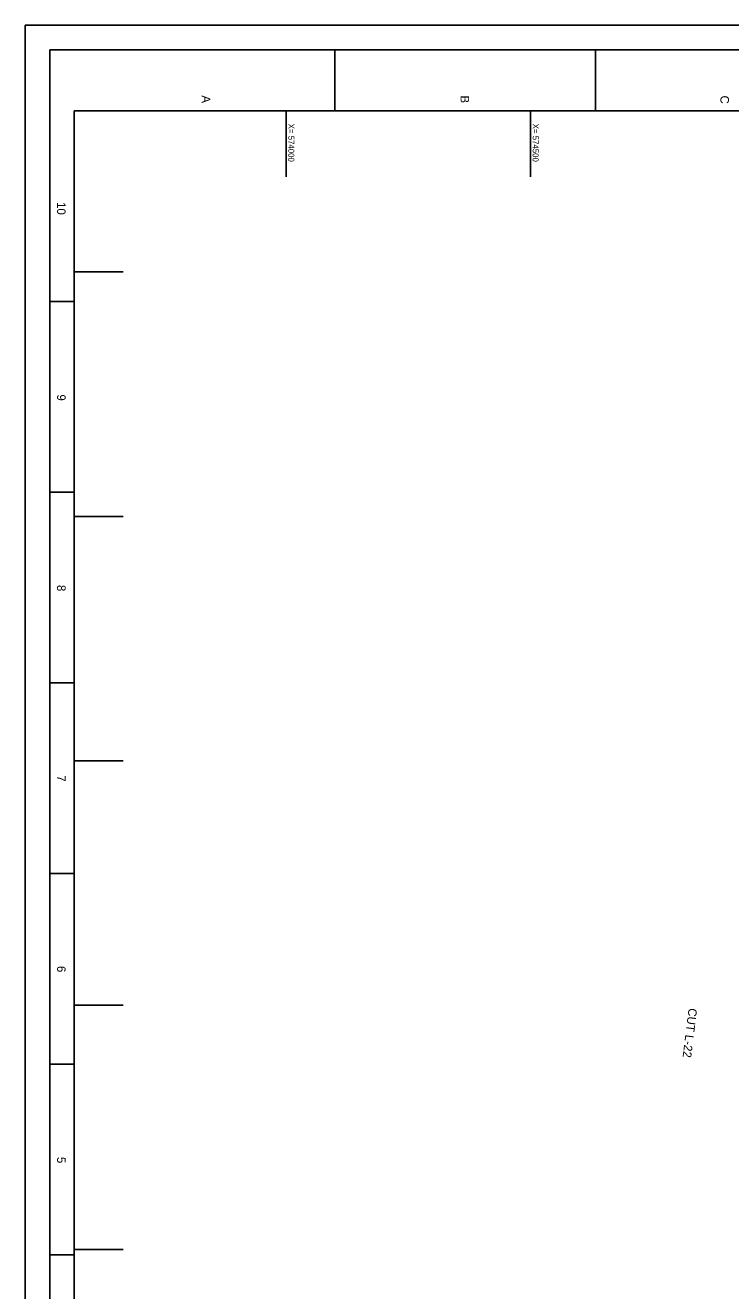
# Model space of a CAD drawing. Extents: x 573466 to 576866, y 874104 to 878505.
# Drawn here: x 573466 to 574910, y 875916 to 878505 of the extents above; entities that cross this region are included whole.
import ezdxf

# ---------------------------------------------------------------- set-up
doc = ezdxf.new("R2010")
doc.units = 0
for name, color, linetype in [('G-ANNO-NPLT', 7, 'Continuous'), ('G-ANNO-TTLB', 7, 'Continuous'), ('V-CHAN-CNTR-IDEN', 7, 'Continuous'), ('V-TOPO-COOR-STAT', 7, 'Continuous')]:
    doc.layers.add(name, color=color, linetype=linetype)

msp = doc.modelspace()

# ---------------------------------------------------------------- linework, layer by layer
at = {"layer": 'G-ANNO-NPLT'}
msp.add_lwpolyline([(576866.5, 878504.6), (576866.5, 874104.6), (573466.5, 874104.6), (573466.5, 878504.6)], close=True, dxfattribs=at)
msp.add_lwpolyline([(573516.5, 878504.6), (573466.5, 878504.6), (573466.5, 878454.6)], dxfattribs=at)
at = {"layer": 'G-ANNO-TTLB'}
for p, q in [((574099.8, 878454.6), (574099.8, 878329.6)), ((574633.1, 878454.6), (574633.1, 878329.6)), ((573516.5, 877939.6), (573566.5, 877939.6)), ((573516.5, 877549.6), (573566.5, 877549.6)), ((573516.5, 877159.6), (573566.5, 877159.6)), ((573516.5, 876769.6), (573566.5, 876769.6)), ((573516.5, 876379.6), (573566.5, 876379.6)), ((573516.5, 875989.6), (573566.5, 875989.6))]:
    msp.add_line(p, q, dxfattribs=at)
for points in [[(573516.5, 878454.6), (573516.5, 874154.6), (576816.5, 874154.6), (576816.5, 878454.6)], [(576766.5, 874204.6), (576766.5, 878329.6), (573566.5, 878329.6), (573566.5, 874204.6)]]:
    msp.add_lwpolyline(points, close=True, dxfattribs=at)
at = {"layer": 'V-TOPO-COOR-STAT'}
for p, q in [((574000, 878194.6), (574000, 878329.6)), ((574500, 878194.6), (574500, 878329.6)), ((573566.7, 878000), (573666.5, 878000)), ((573566.7, 877500), (573666.5, 877500)), ((573566.7, 877000), (573666.5, 877000)), ((573564.8, 876500), (573666.5, 876500)), ((573566.7, 876000), (573666.5, 876000))]:
    msp.add_line(p, q, dxfattribs=at)

# ---------------------------------------------------------------- texts
at = {"layer": 'G-ANNO-TTLB'}
for s, p in [('A', (573827.7, 878361.2)), ('B', (574357.2, 878361)), ('C', (574889, 878360.9)), ('10', (573531.5, 878143)), ('9', (573531.5, 877749.5)), ('8', (573531.5, 877359.7)), ('7', (573531.5, 876970.2)), ('6', (573531.5, 876580.3)), ('5', (573531.5, 876189.5))]:
    msp.add_text(s, height=17.5, rotation=270, dxfattribs=at).set_placement(p)
at = {"layer": 'V-CHAN-CNTR-IDEN'}
msp.add_text('CUT L-22', height=17.52, rotation=262.9998, dxfattribs=at).set_placement((574824, 876494.6))
at = {"layer": 'V-TOPO-COOR-STAT'}
for s, p in [('X= 574000', (574004.8, 878303.3)), ('X= 574500', (574504.8, 878303.3))]:
    msp.add_text(s, height=12, rotation=270, dxfattribs=at).set_placement(p)

doc.saveas('drawing.dxf')
